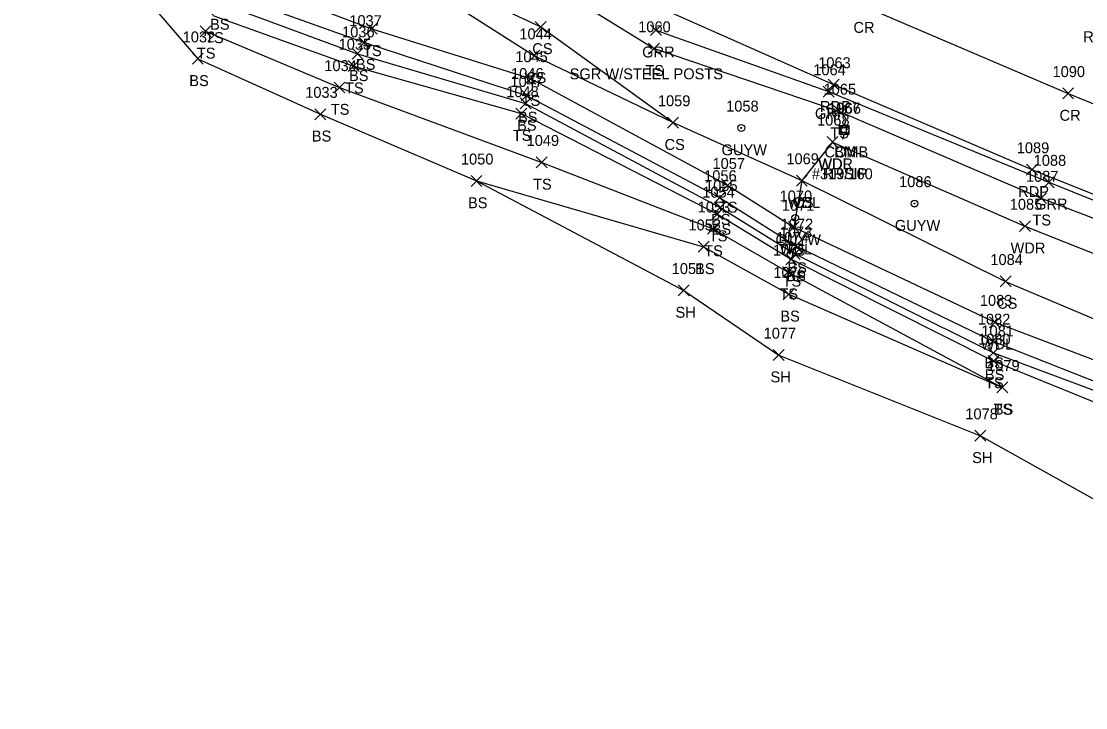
# Model space of a CAD drawing. Extents: x 1547013 to 1549434, y 267998 to 268739.
# Drawn here: x 1548272.6 to 1548467.5, y 268041.1 to 268166.7 of the extents above; entities that cross this region are included whole.
import ezdxf

# ---------------------------------------------------------------- set-up
doc = ezdxf.new("R2010")
doc.units = 0
for name, color, linetype in [('C_A', 7, 'Continuous'), ('C_C', 7, 'Continuous'), ('C_I', 7, 'Continuous'), ('CPBM', 7, 'Continuous'), ('L_A', 7, 'Continuous'), ('L_I', 7, 'Continuous'), ('L_TIC', 7, 'Continuous'), ('LAWA', 7, 'Continuous'), ('LELB', 7, 'Continuous'), ('LSOGP', 7, 'Continuous'), ('P_A', 7, 'Continuous'), ('P_I', 7, 'Continuous'), ('P_TIC', 7, 'Continuous'), ('PET', 7, 'Continuous'), ('PRC', 7, 'Continuous'), ('R_A', 7, 'Continuous'), ('R_C', 7, 'Continuous'), ('R_I', 7, 'Continuous'), ('R_TIC', 7, 'Continuous'), ('RGR', 7, 'Continuous'), ('U_A', 7, 'Continuous'), ('U_C', 7, 'Continuous'), ('U_I', 7, 'Continuous'), ('UP', 7, 'Continuous'), ('UPGW', 7, 'Continuous')]:
    doc.layers.add(name, color=color, linetype=linetype)

msp = doc.modelspace()

# ---------------------------------------------------------------- linework, layer by layer
at = {"layer": 'CPBM'}
for p, q in [((1548422.62, 268146.33), (1548422.62, 268147.33)), ((1548422.62, 268147.33), (1548423.62, 268147.33)), ((1548423.62, 268147.33), (1548423.62, 268146.33)), ((1548423.62, 268146.33), (1548422.62, 268146.33)), ((1548423.12, 268146.83), (1548423.12, 268146.83)), ((1548423.12, 268146.83), (1548423.12, 268146.83))]:
    msp.add_line(p, q, dxfattribs=at)
at = {"layer": 'L_TIC'}
for points in [[(1548366.71, 268164.7), (1548368.71, 268166.7)], [(1548368.71, 268164.7), (1548366.71, 268166.7)], [(1548305.31, 268163.88), (1548307.31, 268165.88)], [(1548307.31, 268163.88), (1548305.31, 268165.88)], [(1548335.75, 268164.34), (1548337.75, 268166.34)], [(1548337.75, 268164.34), (1548335.75, 268166.34)], [(1548334.42, 268161.83), (1548336.42, 268163.83)], [(1548336.42, 268161.83), (1548334.42, 268163.83)], [(1548387.46, 268160.7), (1548389.46, 268162.7)], [(1548389.46, 268160.7), (1548387.46, 268162.7)], [(1548303.9, 268158.85), (1548305.9, 268160.85)], [(1548305.9, 268158.85), (1548303.9, 268160.85)], [(1548333.15, 268159.77), (1548335.15, 268161.77)], [(1548335.15, 268159.77), (1548333.15, 268161.77)], [(1548365.56, 268159.4), (1548367.56, 268161.4)], [(1548367.56, 268159.4), (1548365.56, 268161.4)], [(1548332.45, 268157.51), (1548334.45, 268159.51)], [(1548334.45, 268157.51), (1548332.45, 268159.51)], [(1548364.8, 268155.23), (1548366.8, 268157.23)], [(1548366.8, 268155.23), (1548364.8, 268157.23)], [(1548329.85, 268153.59), (1548331.85, 268155.59)], [(1548331.85, 268153.59), (1548329.85, 268155.59)], [(1548364.1, 268152.15), (1548366.1, 268154.15)], [(1548366.1, 268152.15), (1548364.1, 268154.15)], [(1548363.93, 268150.69), (1548365.93, 268152.69)], [(1548365.93, 268150.69), (1548363.93, 268152.69)], [(1548421.32, 268149.28), (1548423.32, 268151.28)], [(1548423.32, 268149.28), (1548421.32, 268151.28)], [(1548326.34, 268148.7), (1548328.34, 268150.7)], [(1548328.34, 268148.7), (1548326.34, 268150.7)], [(1548363.16, 268148.82), (1548365.16, 268150.82)], [(1548365.16, 268148.82), (1548363.16, 268150.82)], [(1548390.94, 268147.16), (1548392.94, 268149.16)], [(1548392.94, 268147.16), (1548390.94, 268149.16)], [(1548390.94, 268147.16), (1548392.94, 268149.16)], [(1548392.94, 268147.16), (1548390.94, 268149.16)], [(1548420.13, 268143.61), (1548422.13, 268145.61)], [(1548422.13, 268143.61), (1548420.13, 268145.61)], [(1548420.13, 268143.61), (1548422.13, 268145.61)], [(1548422.13, 268143.61), (1548420.13, 268145.61)], [(1548366.89, 268139.89), (1548368.89, 268141.89)], [(1548368.89, 268139.89), (1548366.89, 268141.89)], [(1548354.94, 268136.49), (1548356.94, 268138.49)], [(1548356.94, 268136.49), (1548354.94, 268138.49)], [(1548400.93, 268135.68), (1548402.93, 268137.68)], [(1548402.93, 268135.68), (1548400.93, 268137.68)], [(1548414.52, 268136.54), (1548416.52, 268138.54)], [(1548416.52, 268136.54), (1548414.52, 268138.54)], [(1548414.52, 268136.54), (1548416.52, 268138.54)], [(1548416.52, 268136.54), (1548414.52, 268138.54)], [(1548399.46, 268133.44), (1548401.46, 268135.44)], [(1548401.46, 268133.44), (1548399.46, 268135.44)], [(1548399.57, 268131.64), (1548401.57, 268133.64)], [(1548401.57, 268131.64), (1548399.57, 268133.64)], [(1548458.33, 268133.33), (1548460.33, 268135.33)], [(1548460.33, 268133.33), (1548458.33, 268135.33)], [(1548399.06, 268130.43), (1548401.06, 268132.43)], [(1548401.06, 268130.43), (1548399.06, 268132.43)], [(1548398.22, 268127.71), (1548400.22, 268129.71)], [(1548400.22, 268127.71), (1548398.22, 268129.71)], [(1548413.05, 268128.03), (1548415.05, 268130.03)], [(1548415.05, 268128.03), (1548413.05, 268130.03)], [(1548413.05, 268128.03), (1548415.05, 268130.03)], [(1548415.05, 268128.03), (1548413.05, 268130.03)], [(1548455.38, 268128.21), (1548457.38, 268130.21)], [(1548457.38, 268128.21), (1548455.38, 268130.21)], [(1548396.53, 268124.43), (1548398.53, 268126.43)], [(1548398.53, 268124.43), (1548396.53, 268126.43)], [(1548413.42, 268124.58), (1548415.42, 268126.58)], [(1548415.42, 268124.58), (1548413.42, 268126.58)], [(1548412.58, 268122.14), (1548414.58, 268124.14)], [(1548414.58, 268122.14), (1548412.58, 268124.14)], [(1548413.23, 268123.12), (1548415.23, 268125.12)], [(1548415.23, 268123.12), (1548413.23, 268125.12)], [(1548412, 268119.81), (1548414, 268121.81)], [(1548414, 268119.81), (1548412, 268121.81)], [(1548451.83, 268118.09), (1548453.83, 268120.09)], [(1548453.83, 268118.09), (1548451.83, 268120.09)], [(1548392.9, 268116.44), (1548394.9, 268118.44)], [(1548394.9, 268116.44), (1548392.9, 268118.44)], [(1548412.13, 268115.74), (1548414.13, 268117.74)], [(1548414.13, 268115.74), (1548412.13, 268117.74)], [(1548449.89, 268110.62), (1548451.89, 268112.62)], [(1548451.89, 268110.62), (1548449.89, 268112.62)], [(1548449.52, 268107.18), (1548451.52, 268109.18)], [(1548451.52, 268107.18), (1548449.52, 268109.18)], [(1548410.29, 268104.61), (1548412.29, 268106.61)], [(1548412.29, 268104.61), (1548410.29, 268106.61)], [(1548449.61, 268105.02), (1548451.61, 268107.02)], [(1548451.61, 268105.02), (1548449.61, 268107.02)], [(1548449.66, 268103.52), (1548451.66, 268105.52)], [(1548451.66, 268103.52), (1548449.66, 268105.52)], [(1548449.66, 268103.52), (1548451.66, 268105.52)], [(1548451.66, 268103.52), (1548449.66, 268105.52)], [(1548451.23, 268098.69), (1548453.23, 268100.69)], [(1548453.23, 268098.69), (1548451.23, 268100.69)], [(1548451.23, 268098.69), (1548453.23, 268100.69)], [(1548453.23, 268098.69), (1548451.23, 268100.69)], [(1548447.23, 268089.84), (1548449.23, 268091.84)], [(1548449.23, 268089.84), (1548447.23, 268091.84)]]:
    msp.add_lwpolyline(points, dxfattribs=at)
at = {"layer": 'LAWA'}
for points in [[(1548421.13, 268144.61), (1548415.52, 268137.54), (1548414.05, 268129.03), (1548450.89, 268111.62), (1548480.87, 268100.25), (1548525.53, 268082.58), (1548525.56, 268079.65), (1548525.1, 268077.98), (1548524.33, 268076.7), (1548514.72, 268061.84), (1548494.63, 268042.02)], [(1548421.13, 268144.61), (1548456.38, 268129.21), (1548489.15, 268116.23), (1548515.82, 268105.35), (1548565.81, 268089.46), (1548595.41, 268078.87)]]:
    msp.add_lwpolyline(points, dxfattribs=at)
at = {"layer": 'LELB'}
for points in [[(1548272.57, 268212.48), (1548289.14, 268210.26), (1548307.62, 268202.44), (1548323.1, 268196.35), (1548369.71, 268173.31), (1548388.46, 268161.7), (1548422.32, 268150.28), (1548459.33, 268134.33), (1548490.6, 268122.37), (1548528.34, 268109.13), (1548567.41, 268095.24), (1548592.2, 268086.56), (1548606.66, 268079.82), (1548620.32, 268072.15), (1548638.75, 268065.65), (1548644.4, 268061.61), (1548647.64, 268052.81), (1548649.6, 268041.05)], [(1548289.24, 268200.12), (1548292.11, 268199.39), (1548293.23, 268192.21), (1548309.74, 268172.03), (1548335.42, 268162.83), (1548365.1, 268153.15), (1548400.46, 268134.44), (1548414.42, 268125.58), (1548450.52, 268108.18), (1548480.18, 268096.43), (1548525.56, 268079.65), (1548533.49, 268078.22), (1548538.36, 268080.07), (1548548.83, 268079.87)], [(1548289.24, 268200.12), (1548291.1, 268191.14), (1548308.71, 268170.17), (1548334.15, 268160.77), (1548364.93, 268151.69), (1548400.57, 268132.64), (1548414.23, 268124.12), (1548450.61, 268106.02), (1548479.71, 268095.13), (1548525.1, 268077.98), (1548532.42, 268076.13)], [(1548294.8, 268200.12), (1548295.49, 268192.38), (1548311.68, 268174.8), (1548336.75, 268165.34), (1548365.8, 268156.23), (1548401.93, 268136.68), (1548414.05, 268129.03)], [(1548284.5, 268198.5), (1548285.22, 268192.65), (1548307.82, 268167.72), (1548333.45, 268158.51), (1548364.16, 268149.82), (1548400.06, 268131.43), (1548413.58, 268123.14), (1548450.66, 268104.52)], [(1548306.43, 268199.29), (1548321.43, 268192.43), (1548332.78, 268181.9), (1548367.71, 268165.7), (1548391.94, 268148.16), (1548415.52, 268137.54), (1548452.83, 268119.09), (1548479.13, 268107.94), (1548530.85, 268089.69)], [(1548332.78, 268181.9), (1548366.56, 268160.4), (1548391.94, 268148.16)], [(1548306.31, 268164.88), (1548330.85, 268154.59), (1548367.89, 268140.89), (1548399.22, 268128.71), (1548413, 268120.81), (1548452.23, 268099.69)], [(1548304.9, 268159.85), (1548327.34, 268149.7), (1548355.94, 268137.49), (1548397.53, 268125.43), (1548413.13, 268116.74), (1548452.23, 268099.69)], [(1548450.66, 268104.52), (1548479.47, 268092.8), (1548524.33, 268076.7)]]:
    msp.add_lwpolyline(points, dxfattribs=at)
at = {"layer": 'LSOGP'}
msp.add_lwpolyline([(1548289.82, 268177.4), (1548304.9, 268159.85), (1548327.34, 268149.7), (1548355.94, 268137.49), (1548393.9, 268117.44), (1548411.29, 268105.61), (1548448.23, 268090.84), (1548475.05, 268075.85)], dxfattribs=at)
at = {"layer": 'P_TIC'}
for points in [[(1548420.34, 268154.12), (1548422.34, 268156.12)], [(1548422.34, 268154.12), (1548420.34, 268156.12)], [(1548463.29, 268152.5), (1548465.29, 268154.5)], [(1548465.29, 268152.5), (1548463.29, 268154.5)], [(1548456.66, 268138.55), (1548458.66, 268140.55)], [(1548458.66, 268138.55), (1548456.66, 268140.55)]]:
    msp.add_lwpolyline(points, dxfattribs=at)
at = {"layer": 'PET'}
msp.add_lwpolyline([(1548277.31, 268222.58), (1548324.08, 268200.05), (1548370.89, 268177.56), (1548421.34, 268155.12), (1548457.66, 268139.55), (1548491.25, 268126.1), (1548528.96, 268112.02), (1548568.2, 268099.41), (1548604.28, 268089.49), (1548621.9, 268083.87), (1548638.12, 268079.83), (1548660.94, 268075.04), (1548683.04, 268070.81), (1548718.59, 268065.27), (1548750.02, 268060.75), (1548786.09, 268057.26), (1548818, 268054.36), (1548866.14, 268051.84)], dxfattribs=at)
at = {"layer": 'PRC'}
msp.add_lwpolyline([(1548285.23, 268237.15), (1548330.43, 268214.75), (1548376.37, 268192.58), (1548426.54, 268169.59), (1548464.29, 268153.5), (1548497.35, 268140.09), (1548534.69, 268126.49), (1548572.93, 268114.69), (1548608.02, 268104.77), (1548637.81, 268097.38), (1548663.07, 268091.69), (1548686.38, 268086.96), (1548723.69, 268081.05), (1548751.9, 268076.9), (1548786.74, 268073.36), (1548818.76, 268070.54), (1548866.8, 268068.08)], dxfattribs=at)
at = {"layer": 'R_TIC'}
for points in [[(1548387.8, 268164.09), (1548389.8, 268166.09)], [(1548389.8, 268164.09), (1548387.8, 268166.09)], [(1548419.43, 268152.83), (1548421.43, 268154.83)], [(1548421.43, 268152.83), (1548419.43, 268154.83)], [(1548459.75, 268136.25), (1548461.75, 268138.25)], [(1548461.75, 268136.25), (1548459.75, 268138.25)]]:
    msp.add_lwpolyline(points, dxfattribs=at)
at = {"layer": 'RGR'}
msp.add_lwpolyline([(1548388.8, 268165.09), (1548420.43, 268153.83), (1548460.75, 268137.25), (1548490.9, 268125.1), (1548529.02, 268110.81), (1548568.38, 268097.87), (1548602.59, 268086.19)], dxfattribs=at)
at = {"layer": 'UP'}
for p, q in [((1548422.44, 268145.96), (1548422.44, 268147.63)), ((1548422.44, 268147.63), (1548424.11, 268147.63)), ((1548423.53, 268148.46), (1548423.28, 268147.63)), ((1548424.11, 268147.63), (1548424.11, 268145.96)), ((1548424.11, 268145.96), (1548422.44, 268145.96)), ((1548423.03, 268145.13), (1548423.28, 268145.96)), ((1548423.28, 268146.79), (1548423.28, 268146.79))]:
    msp.add_line(p, q, dxfattribs=at)
msp.add_circle((1548423.28, 268146.79), 0.833, dxfattribs=at)
at = {"layer": 'UPGW'}
for centre, radius in [((1548404.43, 268147.18), 0.625), ((1548404.43, 268147.18), 0.0833), ((1548436.15, 268133.35), 0.625), ((1548436.15, 268133.35), 0.0833), ((1548414.31, 268130.73), 0.625), ((1548414.31, 268130.73), 0.0833)]:
    msp.add_circle(centre, radius, dxfattribs=at)

# ---------------------------------------------------------------- texts
at = {"layer": 'C_A'}
msp.add_text('BM', height=2, dxfattribs=at).set_placement((1548421.44, 268141.83))
at = {"layer": 'C_C'}
msp.add_text('RRSIP', height=2, dxfattribs=at).set_placement((1548419.33, 268137.83))
at = {"layer": 'C_I'}
msp.add_text('1067', height=2, dxfattribs=at).set_placement((1548420.3, 268149.83))
at = {"layer": 'L_A'}
for s, p in [('BS', (1548307.15, 268165.17)), ('TS', (1548306.23, 268162.72)), ('CS', (1548366.16, 268160.7)), ('TS', (1548304.72, 268159.88)), ('TS', (1548335.16, 268160.34)), ('BS', (1548333.86, 268157.83)), ('BS', (1548303.34, 268154.85)), ('BS', (1548332.59, 268155.77)), ('CS', (1548365, 268155.4)), ('TS', (1548386.87, 268156.7)), ('TS', (1548331.86, 268153.51)), ('TS', (1548364.21, 268151.23)), ('TS', (1548329.25, 268149.59)), ('BS', (1548363.54, 268148.15)), ('BS', (1548363.37, 268146.69)), ('TS', (1548420.73, 268145.28)), ('BS', (1548325.78, 268144.7)), ('TS', (1548362.57, 268144.82)), ('CS', (1548390.38, 268143.16)), ('CS', (1548390.38, 268143.16)), ('WDR', (1548418.49, 268139.61)), ('WDL', (1548418.55, 268139.61)), ('TS', (1548366.3, 268135.89)), ('BS', (1548354.38, 268132.49)), ('TS', (1548400.34, 268131.68)), ('WDL', (1548412.94, 268132.54)), ('CS', (1548413.96, 268132.54)), ('BS', (1548398.9, 268129.44)), ('BS', (1548399.01, 268127.64)), ('TS', (1548457.74, 268129.33)), ('TS', (1548398.47, 268126.43)), ('TS', (1548397.63, 268123.71)), ('WDL', (1548411.47, 268124.03)), ('TS', (1548412.46, 268124.03)), ('WDR', (1548453.74, 268124.21)), ('BS', (1548395.97, 268120.43)), ('BS', (1548412.86, 268120.58)), ('TS', (1548411.99, 268118.14)), ('BS', (1548412.67, 268119.12)), ('TS', (1548411.41, 268115.81)), ('CS', (1548451.27, 268114.09)), ('SH', (1548392.38, 268112.44)), ('BS', (1548411.58, 268111.74)), ('WDL', (1548448.31, 268106.62)), ('BS', (1548448.96, 268103.18)), ('SH', (1548409.78, 268100.61)), ('BS', (1548449.05, 268101.02)), ('TS', (1548449.07, 268099.52)), ('TS', (1548449.07, 268099.52)), ('TS', (1548450.64, 268094.69)), ('BS', (1548450.67, 268094.69)), ('SH', (1548446.71, 268085.84))]:
    msp.add_text(s, height=2, dxfattribs=at).set_placement(p)
at = {"layer": 'L_I'}
for s, p in [('1037', (1548332.65, 268165.83)), ('1060', (1548385.55, 268164.7)), ('1032', (1548302.13, 268162.85)), ('1036', (1548331.33, 268163.77)), ('1044', (1548363.79, 268163.4)), ('1035', (1548330.68, 268161.51)), ('1045', (1548363.03, 268159.23)), ('1034', (1548328.07, 268157.59)), ('1046', (1548362.27, 268156.15)), ('1048', (1548361.39, 268152.82)), ('1047', (1548362.16, 268154.69)), ('1065', (1548419.5, 268153.28)), ('1033', (1548324.57, 268152.7)), ('1059', (1548389.16, 268151.16)), ('1059', (1548389.16, 268151.16)), ('1068', (1548418.31, 268147.61)), ('1068', (1548418.31, 268147.61)), ('1049', (1548365.11, 268143.89)), ('1050', (1548353.09, 268140.49)), ('1057', (1548399.16, 268139.68)), ('1069', (1548412.69, 268140.54)), ('1069', (1548412.69, 268140.54)), ('1056', (1548397.63, 268137.44)), ('1087', (1548456.56, 268137.33)), ('1055', (1548397.8, 268135.64)), ('1054', (1548397.29, 268134.43)), ('1053', (1548396.45, 268131.71)), ('1071', (1548411.85, 268132.03)), ('1071', (1548411.85, 268132.03)), ('1085', (1548453.6, 268132.21)), ('1052', (1548394.76, 268128.43)), ('1072', (1548411.64, 268128.58)), ('1074', (1548410.81, 268126.14)), ('1073', (1548411.46, 268127.12)), ('1075', (1548410.23, 268123.81)), ('1084', (1548450.05, 268122.09)), ('1051', (1548391.69, 268120.44)), ('1076', (1548410.31, 268119.74)), ('1083', (1548448.12, 268114.62)), ('1082', (1548447.75, 268111.18)), ('1077', (1548408.52, 268108.61)), ('1081', (1548448.4, 268109.02)), ('1080', (1548447.8, 268107.52)), ('1080', (1548447.8, 268107.52)), ('1079', (1548449.45, 268102.69)), ('1079', (1548449.45, 268102.69)), ('1078', (1548445.46, 268093.84))]:
    msp.add_text(s, height=2, dxfattribs=at).set_placement(p)
at = {"layer": 'P_A'}
for s, p in [('CR', (1548424.97, 268164.59)), ('RDP', (1548467.05, 268162.88)), ('RDP', (1548418.83, 268150.12)), ('CR', (1548462.72, 268148.5)), ('RDP', (1548455.14, 268134.55))]:
    msp.add_text(s, height=2, dxfattribs=at).set_placement(p)
at = {"layer": 'P_I'}
for s, p in [('1063', (1548418.52, 268158.12)), ('1090', (1548461.43, 268156.5)), ('1089', (1548454.88, 268142.55))]:
    msp.add_text(s, height=2, dxfattribs=at).set_placement(p)
at = {"layer": 'R_A'}
for p in [(1548386.28, 268160.09), (1548417.92, 268148.83), (1548458.24, 268132.25)]:
    msp.add_text('GRR', height=2, dxfattribs=at).set_placement(p)
at = {"layer": 'R_C'}
msp.add_text('SGR W/STEEL POSTS', height=2, dxfattribs=at).set_placement((1548373, 268156.09))
at = {"layer": 'R_I'}
for s, p in [('1064', (1548417.61, 268156.83)), ('1088', (1548457.98, 268140.25))]:
    msp.add_text(s, height=2, dxfattribs=at).set_placement(p)
at = {"layer": 'U_A'}
for s, p in [('GUYW', (1548400.82, 268142.18)), ('COMB', (1548419.66, 268141.79)), ('GUYW', (1548432.55, 268128.35)), ('GUYW', (1548410.7, 268125.73))]:
    msp.add_text(s, height=2, dxfattribs=at).set_placement(p)
at = {"layer": 'U_C'}
msp.add_text('#319/160', height=2, dxfattribs=at).set_placement((1548417.35, 268137.79))
at = {"layer": 'U_I'}
for s, p in [('1058', (1548401.66, 268150.18)), ('1066', (1548420.4, 268149.79)), ('1086', (1548433.33, 268136.35)), ('1070', (1548411.45, 268133.73))]:
    msp.add_text(s, height=2, dxfattribs=at).set_placement(p)

doc.saveas('drawing.dxf')
